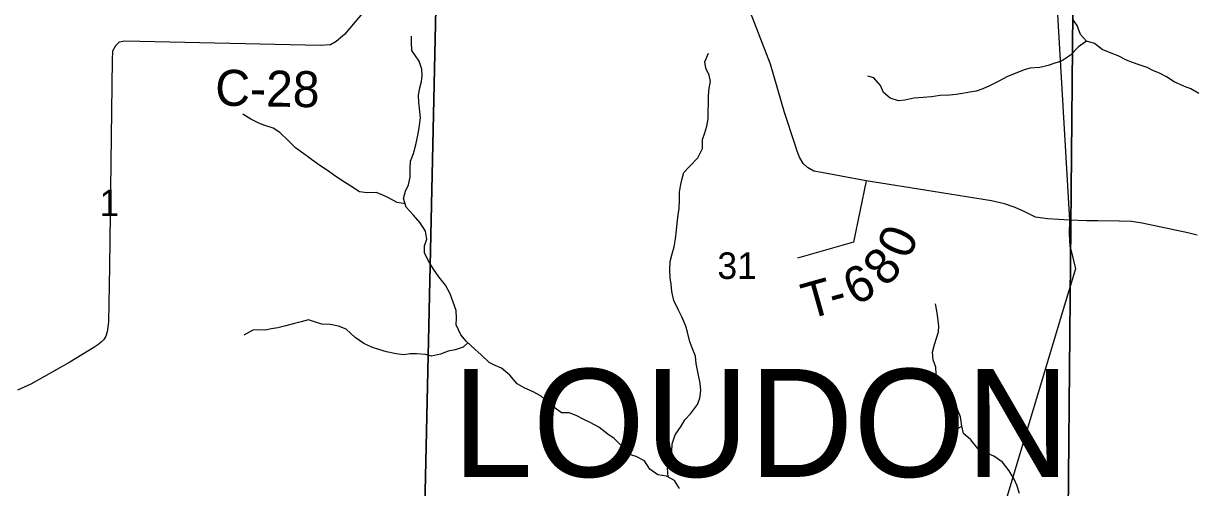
# Model space of a CAD drawing. Extents: x -3.6 to 34, y 0 to 32.8.
# Drawn here: x -0.41 to 1.441, y 29.117 to 29.85 of the extents above; entities that cross this region are included whole.
import ezdxf

# ---------------------------------------------------------------- set-up
doc = ezdxf.new("R2010")
doc.units = 0
for name, color, linetype in [('GM_X_Corporation', 7, 'Continuous'), ('GM_X_County_Road', 7, 'Continuous'), ('GM_X_County_Road_Text', 7, 'Continuous'), ('GM_X_Minor_Lake', 7, 'Continuous'), ('GM_X_Minor_River', 7, 'Continuous'), ('GM_X_Section_Text', 7, 'Continuous'), ('GM_X_Township_Road', 7, 'Continuous'), ('GM_X_Township_Road_Text', 7, 'Continuous'), ('GM_X_Township_Text', 7, 'Continuous')]:
    doc.layers.add(name, color=color, linetype=linetype)

msp = doc.modelspace()

# ---------------------------------------------------------------- linework, layer by layer
at = {"layer": 'GM_X_Corporation'}
for points in [[(-0.7755, 30.0957), (0.2459, 30.0789), (0.244, 29.9924), (0.223, 29.0627), (-0.7627, 29.0764), (-0.7893, 29.0771)], [(1.2483, 29.9822), (1.2386, 28.9647), (0.2524, 28.9828), (0.2209, 28.9831), (0.223, 29.0627), (0.244, 29.9924)], [(2.2535, 29.9602), (2.2411, 28.9502), (1.4051, 28.9619), (1.2386, 28.9647), (1.2483, 29.9822)]]:
    msp.add_lwpolyline(points, close=True, dxfattribs=at)
at = {"layer": 'GM_X_County_Road'}
for points in [[(0.1758, 29.9267), (0.0971, 29.8323), (0.0839, 29.8215), (0.0746, 29.8161), (0.0587, 29.8149), (-0.2499, 29.8219), (-0.2591, 29.8205), (-0.2647, 29.8143), (-0.2696, 29.8059), (-0.2699, 29.7923), (-0.2717, 29.6707), (-0.2742, 29.4665), (-0.2759, 29.3784), (-0.2777, 29.363), (-0.2798, 29.3561), (-0.2831, 29.3511), (-0.2871, 29.3467), (-0.2924, 29.3422), (-0.2991, 29.3381), (-0.3366, 29.315), (-0.3986, 29.2802), (-0.4194, 29.2707)], [(1.4436, 29.5156), (1.4286, 29.5194), (1.3568, 29.5346), (1.3396, 29.5371), (1.3204, 29.5377), (1.2864, 29.538), (1.2688, 29.5383), (1.2419, 29.5394), (1.2068, 29.5413), (1.1883, 29.5441), (1.1712, 29.5522), (1.1559, 29.5592), (1.1391, 29.5651), (1.1184, 29.5699), (1.0267, 29.5847), (0.9208, 29.6016), (0.881, 29.6085), (0.85, 29.6143), (0.8383, 29.6168), (0.8281, 29.6224), (0.8214, 29.6289), (0.8152, 29.6389), (0.8117, 29.648), (0.8079, 29.6599), (0.7918, 29.7093), (0.7696, 29.7854), (0.7256, 29.9001)]]:
    msp.add_lwpolyline(points, dxfattribs=at)
at = {"layer": 'GM_X_Minor_Lake'}
for points in [[(1.0386, 29.2705), (1.04, 29.2558), (1.0427, 29.2471), (1.0483, 29.2305), (1.0522, 29.2211), (1.0546, 29.2135), (1.0604, 29.2079), (1.0716, 29.2141)], [(1.0716, 29.2141), (1.0695, 29.2285), (1.0648, 29.2402), (1.0601, 29.2508), (1.0508, 29.2635), (1.0386, 29.2705)]]:
    msp.add_lwpolyline(points, dxfattribs=at)
at = {"layer": 'GM_X_Minor_River'}
for points in [[(1.4462, 29.7391), (1.4332, 29.7469), (1.4233, 29.7505), (1.4073, 29.7575), (1.3951, 29.7656), (1.384, 29.7712), (1.3745, 29.7752), (1.3646, 29.7804), (1.3516, 29.7847), (1.3414, 29.7883), (1.3318, 29.792), (1.3189, 29.7986), (1.3075, 29.803), (1.2934, 29.8089), (1.2815, 29.8185), (1.2689, 29.8221), (1.2593, 29.8322), (1.2538, 29.8469), (1.2465, 29.8571)], [(0.1945, 29.56), (0.1901, 29.5736), (0.193, 29.585), (0.1978, 29.5953), (0.2006, 29.6071), (0.2008, 29.6215), (0.2013, 29.6325), (0.2057, 29.6447), (0.2093, 29.6581), (0.2114, 29.668), (0.2135, 29.679), (0.2156, 29.6885), (0.2169, 29.7014), (0.216, 29.7109), (0.2143, 29.7257), (0.2138, 29.7359), (0.2151, 29.7462), (0.2183, 29.758), (0.2197, 29.7679), (0.2192, 29.7777), (0.2148, 29.7905), (0.2032, 29.807), (0.2026, 29.8203), (0.2025, 29.8298)], [(1.2689, 29.8221), (1.2562, 29.8128), (1.2432, 29.7998), (1.2293, 29.7904), (1.2184, 29.7872), (1.2079, 29.7837), (1.1947, 29.7804), (1.1799, 29.7791), (1.1701, 29.7766), (1.1562, 29.7711), (1.1438, 29.766), (1.1303, 29.759), (1.1156, 29.7512), (1.1051, 29.7464), (1.0942, 29.7429), (1.0844, 29.7412), (1.0727, 29.7395), (1.0629, 29.7375), (1.0523, 29.7369), (1.0375, 29.7359), (1.024, 29.7342), (1.0107, 29.7329), (0.996, 29.7319), (0.982, 29.7286), (0.9718, 29.7277), (0.9585, 29.7317), (0.9482, 29.741), (0.9431, 29.7519), (0.9327, 29.7639), (0.9232, 29.7668)], [(0.608, 29.1336), (0.6068, 29.1483), (0.6149, 29.1617), (0.6136, 29.1738), (0.6142, 29.1863), (0.6189, 29.2001), (0.6285, 29.2142), (0.6344, 29.2238), (0.6434, 29.2334), (0.6541, 29.248), (0.6581, 29.2583), (0.6595, 29.2701), (0.6585, 29.2818), (0.6561, 29.2943), (0.6524, 29.3128), (0.6511, 29.3246), (0.6471, 29.3348), (0.6424, 29.3472), (0.6384, 29.3623), (0.6359, 29.3721), (0.6297, 29.3868), (0.6242, 29.3974), (0.6172, 29.4124), (0.6139, 29.4268), (0.613, 29.4382), (0.6113, 29.448), (0.6104, 29.4609), (0.6113, 29.4738), (0.6142, 29.486), (0.6174, 29.497), (0.6195, 29.51), (0.6211, 29.5236), (0.6221, 29.5346), (0.6238, 29.5476), (0.6255, 29.5575), (0.6261, 29.5704), (0.6259, 29.5833), (0.6273, 29.5928), (0.6294, 29.6027), (0.6326, 29.6145), (0.6416, 29.6241), (0.655, 29.6376), (0.6623, 29.6525), (0.6625, 29.6669), (0.6657, 29.6772), (0.6693, 29.6878), (0.6711, 29.6993), (0.6713, 29.7099), (0.6718, 29.7247), (0.6716, 29.7361), (0.673, 29.7475), (0.6747, 29.7581), (0.673, 29.7683), (0.6676, 29.7792), (0.6659, 29.7894), (0.6717, 29.8032)], [(0.1929, 29.5651), (0.18, 29.567), (0.1663, 29.5744), (0.1564, 29.5795), (0.1469, 29.5828), (0.1325, 29.5826), (0.1204, 29.5839), (0.107, 29.5928), (0.0913, 29.6028), (0.0795, 29.6106), (0.0699, 29.6176), (0.0565, 29.6269), (0.0427, 29.6366), (0.0328, 29.644), (0.0194, 29.6533), (0.0082, 29.6653), (-0.0052, 29.6779), (-0.0155, 29.6846), (-0.0288, 29.689), (-0.0383, 29.6926), (-0.0509, 29.6985), (-0.0635, 29.7066)], [(0.6259, 29.1156), (0.6181, 29.128), (0.6055, 29.135), (0.5919, 29.1374), (0.5792, 29.1463), (0.5707, 29.1591), (0.5574, 29.1661), (0.5452, 29.1697), (0.5352, 29.1817), (0.5229, 29.1944), (0.5129, 29.2015), (0.4984, 29.2126), (0.485, 29.2196), (0.4747, 29.2244), (0.4625, 29.2307), (0.4519, 29.2351), (0.4394, 29.2353), (0.4294, 29.2423), (0.4176, 29.2524), (0.4076, 29.2613), (0.3946, 29.2683), (0.3817, 29.2738), (0.3698, 29.2808), (0.3579, 29.2943), (0.3448, 29.3055), (0.3349, 29.3099), (0.3254, 29.3143), (0.3127, 29.3266), (0.3031, 29.3348), (0.2889, 29.3483), (0.2808, 29.3584), (0.273, 29.3738), (0.274, 29.3845), (0.2731, 29.3966), (0.2687, 29.4098), (0.2636, 29.423), (0.2562, 29.4365), (0.2458, 29.45), (0.2373, 29.462), (0.2299, 29.4741), (0.2232, 29.4872), (0.2231, 29.4986), (0.2271, 29.5093), (0.225, 29.5221), (0.2165, 29.5349), (0.2057, 29.5473), (0.1945, 29.56)], [(1.1629, 29.1078), (1.1586, 29.1206), (1.1543, 29.1304), (1.1465, 29.1436), (1.1361, 29.1571), (1.1223, 29.1664), (1.1094, 29.1722), (1.0968, 29.1785), (1.086, 29.1924), (1.0745, 29.2024), (1.0716, 29.2141), (1.0695, 29.2285), (1.0648, 29.2402), (1.0601, 29.2508), (1.0508, 29.2635), (1.0386, 29.2705), (1.0343, 29.2822), (1.0314, 29.2966), (1.0309, 29.3072), (1.0265, 29.3185), (1.0256, 29.3307), (1.0288, 29.3432), (1.032, 29.3531), (1.0349, 29.3627), (1.0352, 29.3721), (1.0338, 29.385), (1.0321, 29.396), (1.0301, 29.4073)], [(0.2916, 29.3457), (0.2842, 29.3387), (0.2717, 29.3344), (0.2608, 29.3323), (0.2484, 29.3275), (0.2341, 29.3247), (0.2246, 29.3272), (0.2105, 29.3281), (0.2007, 29.328), (0.1905, 29.3267), (0.1784, 29.328), (0.1632, 29.3312), (0.151, 29.3348), (0.1411, 29.338), (0.1274, 29.3443), (0.114, 29.3539), (0.0994, 29.3674), (0.0873, 29.3721), (0.0744, 29.3746), (0.0611, 29.3748), (0.0512, 29.378), (0.0402, 29.382), (0.0285, 29.3788), (0.018, 29.376), (0.004, 29.3724), (-0.0084, 29.3695), (-0.0186, 29.3675), (-0.0284, 29.3654), (-0.0383, 29.366), (-0.0481, 29.3655), (-0.062, 29.3577)]]:
    msp.add_lwpolyline(points, dxfattribs=at)
at = {"layer": 'GM_X_Township_Road'}
for p, q in [((1.2071, 30.1375), (1.2419, 29.5394)), ((1.2353, 29.4101), (0.9908, 28.596))]:
    msp.add_line(p, q, dxfattribs=at)
for points in [[(0.9208, 29.6016), (0.9009, 29.5044), (0.8124, 29.4795)], [(1.2419, 29.5394), (1.2414, 29.5178), (1.2423, 29.4981), (1.2456, 29.4864), (1.2511, 29.4625), (1.2353, 29.4101)]]:
    msp.add_lwpolyline(points, dxfattribs=at)

# ---------------------------------------------------------------- texts
at = {"layer": 'GM_X_County_Road_Text'}
msp.add_text('C-28', height=0.05682, rotation=358.9708, dxfattribs=at).set_placement((-0.1076, 29.7203))
at = {"layer": 'GM_X_Section_Text'}
for s, height, p in [('1', 0.0419, (-0.29, 29.5457)), ('31', 0.04186, (0.6858, 29.4465))]:
    msp.add_text(s, height=height, rotation=0, dxfattribs=at).set_placement(p)
at = {"layer": 'GM_X_Township_Road_Text'}
for s, rotation, p in [('0', 66.6286, (0.9879, 29.4755)), ('8', 46.2341, (0.9515, 29.432)), ('6', 25.8396, (0.9023, 29.4038)), ('T', 15.6424, (0.8286, 29.3822)), ('-', 15.6424, (0.8695, 29.3936))]:
    msp.add_text(s, height=0.0568, rotation=rotation, dxfattribs=at).set_placement(p)
at = {"layer": 'GM_X_Township_Text'}
msp.add_text('LOUDON', height=0.17045, rotation=0, dxfattribs=at).set_placement((0.2673, 29.1339))

doc.saveas('drawing.dxf')
